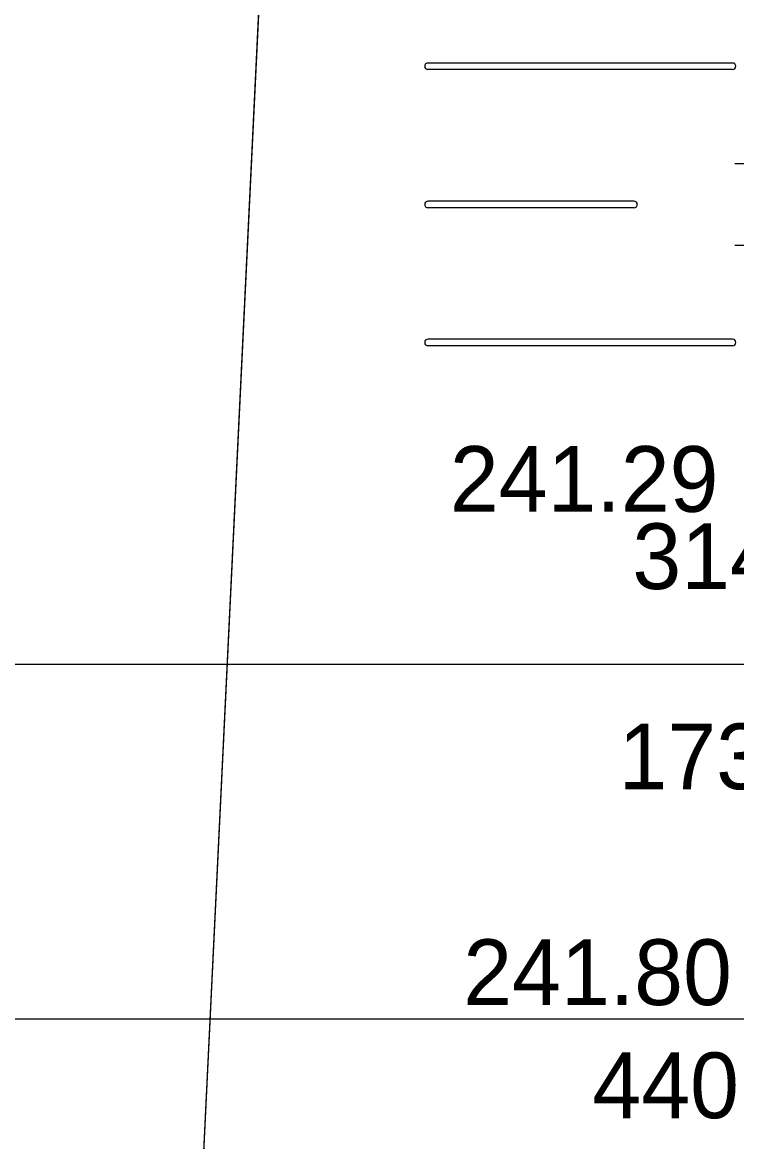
# Model space of a CAD drawing. Extents: x -264205 to -263659, y -1242401 to -1242060.
# Drawn here: x -263915 to -263909.56, y -1242129.52 to -1242121 of the extents above; entities that cross this region are included whole.
import ezdxf

# ---------------------------------------------------------------- set-up
doc = ezdxf.new("R2010")
doc.units = 0
for name, color, linetype in [('BOD_CISLO', 7, 'Continuous'), ('BOD_VYSKA', 7, 'Continuous'), ('KFA_SO_10-1_PLACHTY', 7, 'Continuous'), ('OSI_STAVBY_KFA', 7, 'Continuous'), ('SITUACIA_DSP_2D', 7, 'Continuous')]:
    doc.layers.add(name, color=color, linetype=linetype)

msp = doc.modelspace()

# ---------------------------------------------------------------- linework, layer by layer
at = {"layer": 'KFA_SO_10-1_PLACHTY'}
msp.add_lwpolyline([(-263913.735, -1242131.964), (-263913.734, -1242131.957), (-263912.214, -1242100.448), (-263912.212, -1242100.455)], close=True, dxfattribs=at)
at = {"layer": 'OSI_STAVBY_KFA'}
msp.add_line((-263917.4528, -1242125.8822), (-263905.5048, -1242125.8822), dxfattribs=at)
msp.add_line((-263917.4528, -1242125.8822), (-263905.5048, -1242125.8822), dxfattribs=at)
at = {"layer": 'SITUACIA_DSP_2D'}
for p, q in [((-263909.5936, -1242121.3058), (-263911.9127, -1242121.3058)), ((-263909.5936, -1242121.3558), (-263911.9127, -1242121.3558)), ((-263909.5765, -1242122.0712), (-263909.4815, -1242122.0712)), ((-263910.3436, -1242122.3569), (-263911.9127, -1242122.3569)), ((-263910.3436, -1242122.4069), (-263911.9127, -1242122.4069)), ((-263909.5765, -1242122.6925), (-263909.4815, -1242122.6925)), ((-263909.5936, -1242123.408), (-263911.9127, -1242123.408)), ((-263909.5936, -1242123.458), (-263911.9127, -1242123.458)), ((-263909.0428, -1242128.5822), (-263917.0928, -1242128.5822))]:
    msp.add_line(p, q, dxfattribs=at)
for centre, start, end in [((-263911.9127, -1242121.3308), 90, 270), ((-263909.5936, -1242121.3308), 270, 90), ((-263911.9127, -1242122.3819), 90, 180), ((-263911.9127, -1242122.3819), 180, 270), ((-263910.3436, -1242122.3819), 0, 90), ((-263910.3436, -1242122.3819), 270, 0), ((-263911.9127, -1242123.433), 90, 270), ((-263909.5936, -1242123.433), 270, 90)]:
    msp.add_arc(centre, 0.025, start, end, dxfattribs=at)

# ---------------------------------------------------------------- texts
at = {"layer": 'BOD_CISLO'}
for s, p in [('314', (-263910.3564, -1242125.3098)), ('173', (-263910.4615, -1242126.8333)), ('440', (-263910.6604, -1242129.337))]:
    msp.add_text(s, height=0.5, dxfattribs=at).set_placement(p)
at = {"layer": 'BOD_VYSKA'}
for s, p in [('241.29', (-263911.746, -1242124.7219)), ('241.80', (-263911.6438, -1242128.476))]:
    msp.add_text(s, height=0.5, dxfattribs=at).set_placement(p)

doc.saveas('drawing.dxf')
